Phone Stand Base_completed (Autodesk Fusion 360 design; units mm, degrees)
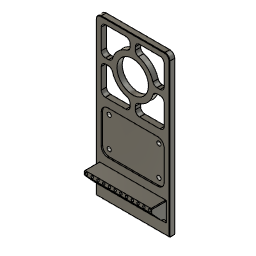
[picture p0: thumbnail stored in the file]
sketch "Sketch1" plane through (0, 0, 0) normal (0, 0, 1) x axis (1, 0, 0)
  line L1 (190.5, 0) -> (0, 0)
  line L2 (190.5, 88.9) -> (190.5, 0)
  line L3 (0, 88.9) -> (190.5, 88.9)
  line L4 (0, 0) -> (0, 88.9)
  point P1 (0, 0)
  point P2 (0, 0)
  point P3 (190.5, 0)
  point P5 (0, 88.9)
  horizontal L1
  vertical L2
  horizontal L3
  vertical L4
  coincident P1 P2
  dimension "d1" distance P2 P3 = 190.5
  dimension "d2" distance P2 P5 = 88.9
extrude "Extrude1" new body sketch "Sketch1" along normal blind 6.35
sketch "Sketch2" plane through (0, 0, 6.35) normal (0, 0, 1) x axis (-1, 0, 0)
  line L1 (0, 0) -> (0, -88.9)
  line L2 (-190.5, 0) -> (0, 0)
  line L3 (-190.5, -88.9) -> (-190.5, 0)
  line L4 (0, -88.9) -> (-190.5, -88.9)
  line L5 (-36.83, -85.09) -> (-19.05, -85.09)
  line L6 (-36.83, -3.81) -> (-36.83, -85.09)
  line L7 (-19.05, -3.81) -> (-36.83, -3.81)
  line L8 (-19.05, -85.09) -> (-19.05, -3.81)
  horizontal L5
  vertical L6
  horizontal L7
  vertical L8
  dimension "d5" distance L1 L8 = 19.05
  dimension "d6" distance L6 L8 = 17.78
  dimension "d7" distance L4 L5 = 3.81
  dimension "d8" distance L2 L7 = 3.81
extrude "Extrude2" add sketch "Sketch2" profile of L5 L6 L7 L8 along normal blind 17.78
fillet "Fillet1" radius 6
chamfer "Chamfer1" distance 12.7 distance 11.43
fillet "Fillet2" radius 6
chamfer "Chamfer2" distance 0.5 distance 0.508
fillet "Fillet4" radius 0.75
sketch "Sketch5" plane through (0, 0, 6.35) normal (0, 0, 1) x axis (-1, 0, 0)
  line L1 (-36.08, -85.09) -> (-13.05, -85.09)
  line L2 (-36.83, -4.56) -> (-36.83, -84.34)
  line L3 (-13.05, -3.81) -> (-36.08, -3.81)
  line L4 (-13.05, -85.09) -> (-13.05, -3.81)
  line L5 (-184.5, -0.5) -> (-0.5, -0.5)
  line L6 (-190, -82.9) -> (-190, -6)
  line L7 (-0.5, -88.4) -> (-184.5, -88.4)
  line L8 (-0.5, -0.5) -> (-0.5, -88.4)
  line L9 (0, -88.9) -> (-184.5, -88.9)
  line L10 (-190.5, -82.9) -> (-190.5, -6)
  line L11 (-184.15, -77.47) -> (-184.15, -52.705)
  line L12 (-154.305, -82.55) -> (-179.07, -82.55)
  line L13 (-184.15, -44.45) -> (-171.45, -44.45)
  line L14 (-190.5, -44.45) -> (-190, -44.45)
  line L15 (-179.07, -47.625) -> (-171.2508, -47.625)
  line L16 (-146.05, -82.55) -> (-146.05, -69.85)
  line L17 (-146.05, -88.9) -> (-146.05, -88.4)
  line L18 (-149.225, -77.47) -> (-149.225, -69.6508)
  line L19 (-149.225, -88.9) -> (-149.225, -88.4)
  arc A1 centre (-36.08, -84.34) radius 0.75 clockwise from (-36.08, -85.09) to (-36.83, -84.34)
  arc A2 centre (-36.08, -4.56) radius 0.75 clockwise from (-36.83, -4.56) to (-36.08, -3.81)
  arc A3 centre (-184.5, -6) radius 5.5 clockwise from (-190, -6) to (-184.5, -0.5)
  arc A4 centre (-184.5, -82.9) radius 5.5 clockwise from (-184.5, -88.4) to (-190, -82.9)
  circle C1 centre (-146.05, -44.45) radius 19.05
  circle C2 centre (-146.05, -44.45) radius 25.4
  arc A5 centre (-179.07, -77.47) radius 5.08 clockwise from (-179.07, -82.55) to (-184.15, -77.47)
  arc A6 centre (-154.305, -77.47) radius 5.08 clockwise from (-149.225, -77.47) to (-154.305, -82.55)
  arc A7 centre (-179.07, -52.705) radius 5.08 clockwise from (-184.15, -52.705) to (-179.07, -47.625)
  point P24 (-149.225, -69.6508)
  point P25 (-146.05, -69.85)
  point P26 (-171.2508, -47.625)
  point P27 (-171.45, -44.45)
  point P28 (-190.5, -44.45)
  point P29 (-184.15, -44.45)
  point P30 (-190, -44.45)
  point P31 (-146.05, -82.55)
  point P32 (-146.05, -88.4)
  point P33 (-149.225, -88.4)
  point P34 (-149.225, -88.9)
  point P35 (-146.05, -88.9)
  point P18 (-146.05, -44.45)
  coincident C2 P24
  coincident C2 P25
  coincident C2 P26
  coincident C2 P27
  coincident L10 P28
  coincident L11 P29
  coincident L6 P30
  collinear L13 L14
  coincident L12 P31
  coincident L7 P32
  collinear L16 L17
  coincident L7 P33
  collinear L18 L19
  coincident L9 P34
  coincident L9 P35
  tangent L12 A5
  tangent L11 A5
  tangent L18 A6
  tangent L12 A6
  tangent L11 A7
  tangent L15 A7
  dimension "d51" distance P18 L9 = 44.45
  dimension "d52" distance P18 L10 = 44.45
  dimension "d53" diameter C1 = 38.1
  dimension "d54" = 6.35
  dimension "d58" radius A5 = 5.08
  dimension "d59" radius A6 = 5.08
  dimension "d60" radius A7 = 5.08
extrude "Extrude5" cut sketch "Sketch5" profile of C1 C2 L19 L15 L11 L12 A5 A6 A7 no distance stored
fillet "Fillet5" radius 5
fillet "Fillet6" radius 5
circular_pattern "C-Pattern1" TotalAngle 360
fillet "Fillet7" radius 5
sketch "Sketch6" plane through (0, 0, 6.35) normal (0, 0, 1) x axis (-1, 0, 0)
  line L1 (-107.95, -77.47) -> (-107.95, -52.705)
  line L2 (-137.795, -82.55) -> (-113.03, -82.55)
  line L3 (-142.875, -73.7302) -> (-142.875, -77.47)
  line L4 (-113.03, -47.625) -> (-116.7698, -47.625)
  line L5 (-113.03, -6.35) -> (-137.795, -6.35)
  line L6 (-107.95, -36.195) -> (-107.95, -11.43)
  line L7 (-116.7698, -41.275) -> (-113.03, -41.275)
  line L8 (-142.875, -11.43) -> (-142.875, -15.1698)
  line L9 (-184.15, -11.43) -> (-184.15, -36.195)
  line L10 (-154.305, -6.35) -> (-179.07, -6.35)
  line L11 (-149.225, -15.1698) -> (-149.225, -11.43)
  line L12 (-179.07, -41.275) -> (-175.3302, -41.275)
  line L13 (-179.07, -82.55) -> (-154.305, -82.55)
  line L14 (-184.15, -52.705) -> (-184.15, -77.47)
  line L15 (-175.3302, -47.625) -> (-179.07, -47.625)
  line L16 (-149.225, -77.47) -> (-149.225, -73.7302)
  line L17 (-36.08, -85.09) -> (-13.05, -85.09)
  line L18 (-36.83, -4.56) -> (-36.83, -84.34)
  line L19 (-13.05, -3.81) -> (-36.08, -3.81)
  line L20 (-13.05, -85.09) -> (-13.05, -3.81)
  line L21 (-184.5, -0.5) -> (-0.5, -0.5)
  line L22 (-190, -82.9) -> (-190, -6)
  line L23 (-0.5, -88.4) -> (-184.5, -88.4)
  line L24 (-0.5, -0.5) -> (-0.5, -88.4)
  line L25 (-46.355, -82.55) -> (-98.425, -82.55)
  line L26 (-46.355, -6.35) -> (-46.355, -82.55)
  line L27 (-98.425, -6.35) -> (-46.355, -6.35)
  line L28 (-98.425, -82.55) -> (-98.425, -6.35)
  line L29 (0, -88.9) -> (-184.5, -88.9)
  arc A1 centre (-113.03, -52.705) radius 5.08 clockwise from (-113.03, -47.625) to (-107.95, -52.705)
  arc A2 centre (-113.03, -77.47) radius 5.08 clockwise from (-107.95, -77.47) to (-113.03, -82.55)
  arc A3 centre (-137.795, -77.47) radius 5.08 clockwise from (-137.795, -82.55) to (-142.875, -77.47)
  arc A4 centre (-137.875, -73.7302) radius 5 clockwise from (-142.875, -73.7302) to (-139.2196, -68.9144)
  arc A5 centre (-146.05, -44.45) radius 25.4 clockwise from (-121.5856, -51.2804) to (-139.2196, -68.9144)
  arc A6 centre (-116.7698, -52.625) radius 5 clockwise from (-121.5856, -51.2804) to (-116.7698, -47.625)
  arc A7 centre (-137.795, -11.43) radius 5.08 clockwise from (-142.875, -11.43) to (-137.795, -6.35)
  arc A8 centre (-113.03, -11.43) radius 5.08 clockwise from (-113.03, -6.35) to (-107.95, -11.43)
  arc A9 centre (-113.03, -36.195) radius 5.08 clockwise from (-107.95, -36.195) to (-113.03, -41.275)
  arc A10 centre (-116.7698, -36.275) radius 5 clockwise from (-116.7698, -41.275) to (-121.5856, -37.6196)
  arc A11 centre (-146.05, -44.45) radius 25.4 clockwise from (-139.2196, -19.9856) to (-121.5856, -37.6196)
  arc A12 centre (-137.875, -15.1698) radius 5 clockwise from (-139.2196, -19.9856) to (-142.875, -15.1698)
  arc A13 centre (-179.07, -36.195) radius 5.08 clockwise from (-179.07, -41.275) to (-184.15, -36.195)
  arc A14 centre (-179.07, -11.43) radius 5.08 clockwise from (-184.15, -11.43) to (-179.07, -6.35)
  arc A15 centre (-154.305, -11.43) radius 5.08 clockwise from (-154.305, -6.35) to (-149.225, -11.43)
  arc A16 centre (-154.225, -15.1698) radius 5 clockwise from (-149.225, -15.1698) to (-152.8804, -19.9856)
  arc A17 centre (-146.05, -44.45) radius 25.4 clockwise from (-170.5144, -37.6196) to (-152.8804, -19.9856)
  arc A18 centre (-175.3302, -36.275) radius 5 clockwise from (-170.5144, -37.6196) to (-175.3302, -41.275)
  arc A19 centre (-154.305, -77.47) radius 5.08 clockwise from (-149.225, -77.47) to (-154.305, -82.55)
  arc A20 centre (-179.07, -77.47) radius 5.08 clockwise from (-179.07, -82.55) to (-184.15, -77.47)
  arc A21 centre (-179.07, -52.705) radius 5.08 clockwise from (-184.15, -52.705) to (-179.07, -47.625)
  arc A22 centre (-175.3302, -52.625) radius 5 clockwise from (-175.3302, -47.625) to (-170.5144, -51.2804)
  arc A23 centre (-146.05, -44.45) radius 25.4 clockwise from (-152.8804, -68.9144) to (-170.5144, -51.2804)
  arc A24 centre (-154.225, -73.7302) radius 5 clockwise from (-152.8804, -68.9144) to (-149.225, -73.7302)
  circle C1 centre (-146.05, -44.45) radius 19.05
  arc A25 centre (-36.08, -84.34) radius 0.75 clockwise from (-36.08, -85.09) to (-36.83, -84.34)
  arc A26 centre (-36.08, -4.56) radius 0.75 clockwise from (-36.83, -4.56) to (-36.08, -3.81)
  arc A27 centre (-184.5, -6) radius 5.5 clockwise from (-190, -6) to (-184.5, -0.5)
  arc A28 centre (-184.5, -82.9) radius 5.5 clockwise from (-184.5, -88.4) to (-190, -82.9)
  horizontal L25
  vertical L26
  horizontal L27
  vertical L28
  dimension "d70" distance L25 L29 = 6.35
  dimension "d71" distance L25 L27 = 76.2
  dimension "d72" distance L6 L28 = 9.525
  dimension "d73" distance L18 L26 = 9.525
extrude "Extrude6" cut sketch "Sketch6" profile of L25 L26 L27 L28 against normal blind 1.6
fillet "Fillet8" radius 8
hole "Hole2" HoleDiameter 5.035 TipAngle 118
hole "Hole3" HoleDiameter 5.035 TipAngle 118
hole "Hole4" HoleDiameter 5.035 TipAngle 118
hole "Hole5" HoleDepth 30.48 HoleDiameter 5.035 TipAngle 118
hole "Hole6" HoleDepth 24.13 HoleDiameter 3 TipAngle 118 RefDim1 2.54 RefDim2 6.35
rectangular_pattern "R-Pattern2" countU 12 uSpaceDistance 76.2 vSpaceDistance 0
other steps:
thread "Thread2"
thread "Thread3"
thread "Thread4"
thread "Thread5"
